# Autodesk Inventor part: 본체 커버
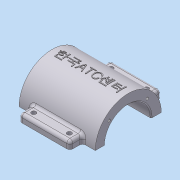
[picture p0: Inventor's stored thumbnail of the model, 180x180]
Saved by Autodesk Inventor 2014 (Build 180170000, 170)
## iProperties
Company: 한국ATC센터
Created: 2014-02
Part Number: 본체 커버
Document SubType Name: Modeling
Designer: KYOUNG IL JANG
Density: 2.71 g/cm^3
Mass: 199.244 g
Surface Area: 195.422 cm^2
Volume: 73.5218 cm^3
Material: 알루미늄-6061
Vendor: CBT Solutions
Appearance: 알루미늄 - 평지
Author: KYOUNG IL JANG
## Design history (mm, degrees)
sketch "스케치1"
  geometry: L1 (-45, 40)-(45, 40); L2 (45, 40)-(45, -40); L3 (45, -40)-(-45, -40); L4 (-45, -40)-(-45, 40); 3 further points
  constraints: 8 end point, 2 midpoint, 2 parallel, 1 horizontal, 1 horizontal alignment, 1 perpendicular, 1 vertical alignment
  dimensions: "d0" = 90 distance of L2.end L3.end; "d1" = 80 distance of L1.end L2.end
extrude "돌출1" new body sketch "스케치1" distance "d2" = 10; taper "d3" = 0 deg
sketch "스케치2"
  geometry: L1 (40, 0)-(-40, 0) reference; C1 r 32.5 at (0, 80); 2 further points
  constraints: 1 centre point, 1 midpoint, 1 vertical alignment
  dimensions: "d4" = 65 diameter of C1; "d5" = 80 distance from line of C1.centre L1
extrude "돌출2" join sketch "스케치2" stored distance "d6" = 75; taper "d7" = 0 deg
sketch "스케치3"
  geometry: L1 (-7.5, -20)-(7.5, -20); L2 (7.5, 20)-(-7.5, 20); A1 r 20 centre (7.5, 0) between (7.5, -20) and (7.5, 20); A2 r 20 centre (-7.5, 0) between (-7.5, 20) and (-7.5, -20); 2 further points
  constraints: 4 end point, 4 point on circle, 4 tangent, 2 centre point, 1 horizontal, 1 horizontal alignment, 1 midpoint, 1 parallel, 1 vertical alignment
  dimensions: "d8" = 20 radius of A2; "d9" = 55 dimension on A1 A2
extrude "돌출3" join sketch "스케치3" stored distance "d10" = 75; taper "d11" = 0 deg
fillet "모깎기1" dims "d12" = 10
sketch "스케치4"
  geometry: L1 (-45, 0)-(-45, 10) reference; L2 (37.5, 47.5)-(-37.5, 47.5) reference; L3 (-45, 10)-(-27.513, 47.5); 1 further point
  constraints: 2 end point, 1 point on line
  dimensions: "d13" = 25 deg angle of L3 L1
sketch "스케치5"
  geometry: L1 (-40, 0)-(-40, 10) reference; L2 (-40, 10)-(-22.912, 56.95); 2 further points
  constraints: 2 end point, 2 other
  dimensions: "d14" = 20 deg angle of L2 L1
feature "리브1" dims "d15" = 1, "d16" = 6, "d17" = 0
feature "리브2" dims "d18" = 1, "d19" = 6, "d20" = 0
fillet "모깎기2" dims "d21" = 3
fillet "모깎기3" dims "d22" = 3
fillet "모깎기4" dims "d23" = 3
fillet "모깎기5" dims "d24" = 3
fillet "모깎기6" dims "d25" = 3
fillet "모깎기7" dims "d26" = 3
fillet "모깎기8" dims "d27" = 3
sketch "스케치6"
  geometry: A1 r 10 centre (35, -30) between (35, -40) and (45, -30) reference; 1 further point
hole "구멍1" sketch "스케치6" at (35, -30) diameter "d28" = 10; stored, may be unused: countersink angle "d32" = 90 deg, drill point angle "d34" = 118 deg; dims "d29" = 6, "d30" = 4, "d31" = 2, "d33" = 8
hole "구멍2" diameter "d37" = 45; stored, may be unused: countersink angle "d41" = 90 deg, drill point angle "d43" = 118 deg; dims "d35" = 10, "d36" = 10, "d38" = 6, "d39" = 4, "d40" = 2, "d42" = 8
sketch "스케치7"
  geometry: C1 r 22.5 at (0, 0) reference; 2 further points
  dimensions: "d44" = 135 deg dimension on C1.centre point (-18.738, 18.738) point (80, 0); "d45" = 26.5 distance of point (-18.738, 18.738) C1.centre
hole "구멍3" sketch "스케치7" at (-18.738, 18.738) diameter "d46" = 2.459; stored, may be unused: countersink angle "d50" = 90 deg, drill point angle "d52" = 118 deg; dims "d47" = 8, "d48" = 4, "d49" = 2, "d51" = 10
node "작업 평면1"
chamfer "모따기1" distance "d69" = 1; stored, may be unused: second distance "d70" = 2, angle "d71" = 45 deg
sketch "스케치9"
  geometry: L1 (-31.623, 87.5)-(-45, 87.5); L2 (-45, 87.5)-(-45, 72.5); L3 (-45, 72.5)-(-31.623, 72.5); A1 r 32.5 centre (0, 80) between (-31.623, 87.5) and (-31.623, 72.5) reference; 1 further point
  constraints: 6 end point, 2 parallel, 2 point on circle, 1 horizontal, 1 perpendicular
  dimensions: "d73" = 15 distance of L1.end L2.end; "d74" = 45 distance from line of A1.centre L2
extrude "돌출5" join sketch "스케치9" stored distance "d75" = 50; taper "d76" = 0 deg
fillet "모깎기10" dims "d77" = 3
fillet "모깎기11" dims "d78" = 3
sketch "스케치10"
  geometry: L1 (100.378, 66.389)-(0, 66.389); L2 (0, 66.389)-(0, -76.978); L3 (0, -76.978)-(100.378, -76.978); L4 (100.378, -76.978)-(100.378, 66.389); C1 r 32.5 at (0, 0) reference; 1 further point
  constraints: 8 end point, 2 parallel, 1 horizontal, 1 perpendicular, 1 point on line
extrude "돌출6" cut sketch "스케치10" stored distance "d79" = 10; taper "d80" = 0 deg
sketch "스케치11"
  geometry: C1 r 1.621 at (4.5, 4) reference; C2 r 1.621 at (39.5, 4) reference; 1 further point
hole "구멍5" sketch "스케치11" at (39.5, 4), (4.5, 4) diameter "d81" = 4.5; stored, may be unused: countersink angle "d85" = 90 deg, drill point angle "d87" = 118 deg; dims "d82" = 6, "d83" = 4, "d84" = 2, "d86" = 8
node "작업 평면2"
sketch "스케치12"
  geometry: 2 further points
  constraints: 1 coincident, 1 other
feature "엠보싱1" sketch "스케치12" dims "d8" = 20, "d9" = 55, "d88" = 0.5, "d89" = 0
node "솔리드1"
mirror "대칭1"
mirror "대칭2"
mirror "대칭3"
mirror "대칭4"
pattern_circular "원형 패턴1" dims angle "d54" = 360 deg
mirror "대칭5"
mirror "대칭6"
mirror "대칭7"
node "참조1"
node "참조2"
other parameters: "d56" = -117
